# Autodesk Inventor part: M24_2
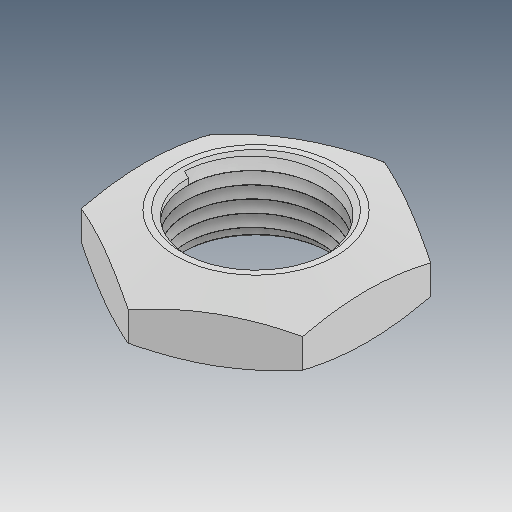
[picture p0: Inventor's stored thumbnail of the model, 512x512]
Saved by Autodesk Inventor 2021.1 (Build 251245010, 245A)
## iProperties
Created: 2019-05
Part Number: M24_2
Material: Ogólny
Document SubType Name: Modeling
Designer: user
Density: 1 g/cm^3
Appearance: Domyślna
Author: user
Revision Number: ÈÎºÎ
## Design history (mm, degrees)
feature "ÊäÈë1"
node "Bryła1"
